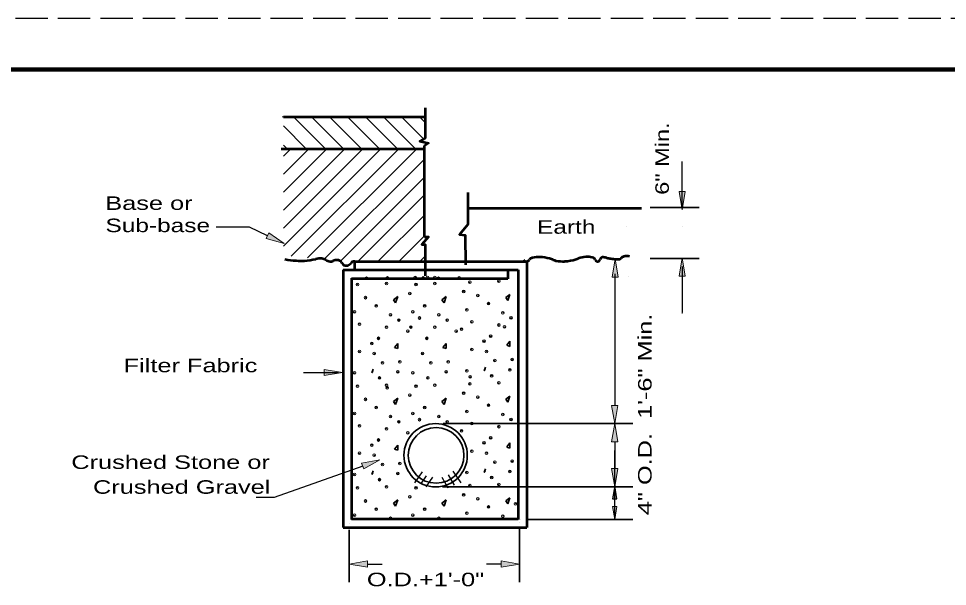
# Model space of a CAD drawing. Extents: x 36 to 71.3, y 0.3 to 22.3.
# Drawn here: x 52.91 to 62.04, y 16.74 to 22.32 of the extents above; entities that cross this region are included whole.
import ezdxf

# ---------------------------------------------------------------- set-up
doc = ezdxf.new("R2010")
doc.units = 0
doc.header["$LTSCALE"] = 0.053
doc.header["$PDMODE"] = 32
doc.header["$PDSIZE"] = 0.0265
doc.linetypes.add('LONG_DASHED', pattern=[7.5, 6, -1.5])
for name, color, linetype, lineweight in [('1', 7, 'Continuous', 13), ('2', 7, 'Continuous', 13), ('4', 7, 'Continuous', 13)]:
    doc.layers.add(name, color=color, linetype=linetype, lineweight=lineweight)

msp = doc.modelspace()

# ---------------------------------------------------------------- hatches: boundary and pattern name
at = {"layer": '1'}
for points in [[(59.40475, 20.6235), (59.46475, 20.6235), (59.43475, 20.4435), (59.43475, 20.4435)], [(58.74733, 19.78192), (58.80733, 19.78192), (58.77733, 19.96192), (58.77733, 19.96192)], [(59.40475, 19.78917), (59.46475, 19.78917), (59.43475, 19.96917), (59.43475, 19.96917)], [(56.34283, 16.98942), (56.34283, 16.92942), (56.16292, 16.95942), (56.16292, 16.95942)], [(57.655, 16.98942), (57.655, 16.92942), (57.835, 16.95942), (57.835, 16.95942)]]:
    msp.add_hatch(color=256, dxfattribs=at).paths.add_polyline_path(points)
at = {"layer": '2'}
for points in [[(55.37283, 20.21533), (55.34692, 20.16117), (55.52225, 20.1105), (55.52225, 20.1105)], [(55.91717, 18.81358), (55.91717, 18.87358), (56.09717, 18.84358), (56.09717, 18.84358)], [(58.74208, 18.51975), (58.80208, 18.51975), (58.77208, 18.33975), (58.77208, 18.33975)], [(58.74208, 18.15983), (58.80208, 18.15983), (58.77208, 18.33975), (58.77208, 18.33975)], [(58.74208, 18.15983), (58.80208, 18.15983), (58.77208, 18.33975), (58.77208, 18.33975)], [(56.28483, 17.95075), (56.30492, 17.89425), (56.4645, 17.98267), (56.4645, 17.98267)], [(58.74208, 17.89733), (58.80208, 17.89733), (58.77208, 17.71733), (58.77208, 17.71733)], [(58.74208, 17.89733), (58.80208, 17.89733), (58.77208, 17.71733), (58.77208, 17.71733)], [(58.75108, 17.602), (58.79308, 17.602), (58.77208, 17.72792), (58.77208, 17.72792)], [(58.75108, 17.52425), (58.79308, 17.52425), (58.77208, 17.39833), (58.77208, 17.39833)]]:
    msp.add_hatch(color=256, dxfattribs=at).paths.add_polyline_path(points)

# ---------------------------------------------------------------- linework, layer by layer
at = {"layer": '1', "linetype": 'LONG_DASHED', "lineweight": 25}
msp.add_line((71.17325, 22.32408), (35.97325, 22.32408), dxfattribs=at)
at = {"layer": '1', "lineweight": 158}
msp.add_line((65.01858, 21.82408), (52.503, 21.82408), dxfattribs=at)
at = {"layer": '1'}
for p, q in [((55.50242, 21.35808), (56.90925, 21.35808)), ((56.90925, 21.35808), (55.53658, 21.35808)), ((56.93842, 21.09575), (56.93258, 21.1015)), ((59.43475, 19.60333), (59.43475, 19.42333))]:
    msp.add_line(p, q, dxfattribs=at)
at = {"layer": '1', "lineweight": 53}
for p, q in [((55.51567, 21.35808), (56.90925, 21.35808)), ((55.49475, 21.04417), (56.90267, 21.04417)), ((56.90225, 20.17425), (56.90225, 21.07158)), ((57.326, 20.46058), (59.03558, 20.46058)), ((56.214, 19.9355), (57.90708, 19.9355)), ((56.214, 19.9355), (56.214, 19.85508)), ((57.90708, 19.9355), (57.90708, 17.31933)), ((56.10183, 19.85217), (56.10183, 17.31933)), ((56.10183, 19.85217), (57.82375, 19.85217)), ((57.72133, 19.85217), (57.72133, 19.765)), ((57.82375, 19.85217), (57.82375, 17.39833)), ((56.18517, 19.76933), (56.18517, 17.39833)), ((56.18517, 19.76883), (57.72133, 19.76883)), ((56.18517, 17.40267), (57.82375, 17.40267)), ((56.10183, 17.31933), (57.90708, 17.31933))]:
    msp.add_line(p, q, dxfattribs=at)
at = {"layer": '1', "lineweight": 35}
for p, q in [((55.92933, 21.04417), (55.61542, 21.35808)), ((56.10608, 21.04417), (55.79217, 21.35808)), ((56.28283, 21.04417), (55.96892, 21.35808)), ((56.45967, 21.04417), (56.14575, 21.35808)), ((56.63642, 21.04417), (56.3225, 21.35808)), ((56.81317, 21.04417), (56.49925, 21.35808)), ((56.89483, 21.13933), (56.67608, 21.35808)), ((56.90925, 21.30167), (56.85283, 21.35808)), ((55.73967, 21.04417), (55.51567, 21.26825)), ((55.55117, 21.04417), (55.51567, 21.07967)), ((55.51567, 20.08625), (56.47358, 21.04417)), ((55.51567, 20.26308), (56.29675, 21.04417)), ((55.51567, 20.43983), (56.12, 21.04417)), ((55.51567, 20.61658), (55.94325, 21.04417)), ((55.51567, 20.79342), (55.7665, 21.04417)), ((55.51567, 20.97017), (55.58967, 21.04417)), ((55.59358, 19.98742), (56.65033, 21.04417)), ((55.75367, 19.97067), (56.82708, 21.04417)), ((55.92425, 19.96458), (56.90225, 20.9425)), ((56.07908, 19.94258), (56.90225, 20.76575)), ((56.24175, 19.92842), (56.90225, 20.589)), ((59.121, 20.46525), (59.60417, 20.46525)), ((56.45483, 19.94358), (56.90225, 20.391)), ((56.65842, 19.94167), (56.90225, 20.18558)), ((56.86758, 19.94475), (56.90225, 19.9795)), ((59.121, 19.96383), (59.60417, 19.96383)), ((56.639, 19.58892), (56.599, 19.55892)), ((56.599, 19.55892), (56.619, 19.52892)), ((56.619, 19.529), (56.639, 19.589)), ((57.11433, 19.58892), (57.07433, 19.55892)), ((57.07433, 19.55892), (57.09433, 19.52892)), ((57.09433, 19.529), (57.11433, 19.589)), ((57.74292, 19.61017), (57.70292, 19.58017)), ((57.70292, 19.58017), (57.72292, 19.55017)), ((57.72292, 19.55025), (57.74292, 19.61025)), ((56.63908, 19.129), (56.60908, 19.089)), ((56.60908, 19.08892), (56.63908, 19.07892)), ((56.639, 19.079), (56.639, 19.129)), ((57.11442, 19.129), (57.08442, 19.089)), ((57.08442, 19.08892), (57.11442, 19.07892)), ((57.11433, 19.079), (57.11433, 19.129)), ((57.743, 19.15025), (57.713, 19.11025)), ((57.713, 19.11017), (57.743, 19.10017)), ((57.74292, 19.10025), (57.74292, 19.15025)), ((56.38375, 18.83892), (56.39817, 18.87492)), ((56.39817, 18.85125), (56.38375, 18.83892)), ((57.48767, 18.86017), (57.50208, 18.89617)), ((57.50208, 18.8725), (57.48767, 18.86017)), ((56.639, 18.58892), (56.599, 18.55892)), ((56.599, 18.55892), (56.619, 18.52892)), ((56.619, 18.529), (56.639, 18.589)), ((57.11433, 18.58892), (57.07433, 18.55892)), ((57.07433, 18.55892), (57.09433, 18.52892)), ((57.09433, 18.529), (57.11433, 18.589)), ((57.74292, 18.61017), (57.70292, 18.58017)), ((57.70292, 18.58017), (57.72292, 18.55017)), ((57.72292, 18.55025), (57.74292, 18.61025)), ((56.63908, 18.129), (56.60908, 18.089)), ((56.60908, 18.08892), (56.63908, 18.07892)), ((56.639, 18.079), (56.639, 18.129)), ((57.743, 18.15025), (57.713, 18.11025)), ((57.713, 18.11017), (57.743, 18.10017)), ((57.74292, 18.10025), (57.74292, 18.15025)), ((57.48767, 17.86017), (57.50208, 17.89617)), ((56.38375, 17.83892), (56.39817, 17.87492)), ((56.39817, 17.85125), (56.38375, 17.83892)), ((57.50208, 17.8725), (57.48767, 17.86017)), ((56.639, 17.58892), (56.599, 17.55892)), ((56.599, 17.55892), (56.619, 17.52892)), ((56.619, 17.529), (56.639, 17.589)), ((57.11433, 17.58892), (57.07433, 17.55892)), ((57.07433, 17.55892), (57.09433, 17.52892)), ((57.09433, 17.529), (57.11433, 17.589)), ((57.74292, 17.61017), (57.70292, 17.58017)), ((57.70292, 17.58017), (57.72292, 17.55017)), ((57.72292, 17.55025), (57.74292, 17.61025)), ((57.91108, 17.39833), (58.95208, 17.39833)), ((56.16292, 17.29392), (56.16292, 16.77942)), ((57.835, 17.302), (57.835, 16.77942))]:
    msp.add_line(p, q, dxfattribs=at)
at = {"layer": '1', "lineweight": 25}
for p, q in [((56.90225, 21.04258), (56.90225, 21.08042)), ((59.43475, 20.46492), (59.43475, 20.91817)), ((59.43475, 19.88708), (59.43475, 19.43383)), ((56.8795, 17.86642), (56.80358, 17.75667)), ((56.86525, 17.74458), (56.92133, 17.82692)), ((56.97975, 17.81317), (56.91475, 17.71717)), ((57.07325, 17.814), (57.13158, 17.70908)), ((57.136, 17.835), (57.1955, 17.73492)), ((57.18225, 17.87367), (57.25825, 17.75667)), ((56.34292, 16.95942), (56.48633, 16.95942)), ((57.655, 16.95942), (57.51158, 16.95942))]:
    msp.add_line(p, q, dxfattribs=at)
at = {"layer": '1', "lineweight": 53}
for points in [[(56.90925, 21.44683), (56.90925, 21.14667), (56.85533, 21.11925), (56.94342, 21.09908), (56.90267, 21.07158)], [(57.32733, 20.61225), (57.32733, 20.29833), (57.24542, 20.20008), (57.30075, 20.19367), (57.306, 19.90308)], [(56.90267, 20.17675), (56.94342, 20.17675), (56.87517, 20.10167), (56.90925, 20.10167), (56.90925, 19.79425)]]:
    msp.add_lwpolyline(points, dxfattribs=at)
at = {"layer": '1'}
for points in [[(59.40475, 20.6235), (59.46475, 20.6235), (59.43475, 20.4435), (59.43475, 20.4435)], [(58.74733, 19.78192), (58.80733, 19.78192), (58.77733, 19.96192), (58.77733, 19.96192)], [(59.40475, 19.78917), (59.46475, 19.78917), (59.43475, 19.96917), (59.43475, 19.96917)], [(56.34283, 16.98942), (56.34283, 16.92942), (56.16292, 16.95942), (56.16292, 16.95942)], [(57.655, 16.98942), (57.655, 16.92942), (57.835, 16.95942), (57.835, 16.95942)]]:
    msp.add_lwpolyline(points, close=True, dxfattribs=at)
at = {"layer": '1', "lineweight": 25}
msp.add_lwpolyline([(58.77208, 19.81275), (58.77208, 19.27417), (58.77208, 18.51683)], dxfattribs=at)
at = {"layer": '1', "lineweight": 35}
for centre, radius in [((57.01217, 18.02867), 0.31134), ((57.01658, 18.02775), 0.27355)]:
    msp.add_circle(centre, radius, dxfattribs=at)
at = {"layer": '1', "lineweight": 53}
for centre, radius, start, end in [((55.72067, 21.05367), 1.11355, 260.16329, 265.88503), ((55.68317, 20.53492), 0.59345, 265.90224, 273.7448), ((55.67308, 20.68308), 0.74198, 273.77126, 282.47695), ((55.87758, 19.75758), 0.20588, 85.82566, 102.39144), ((55.8865, 19.87742), 0.08569, 57.54698, 85.94234), ((55.98267, 20.02833), 0.09327, 237.44355, 264.65422), ((55.97958, 19.99517), 0.05994, 264.67221, 294.75702), ((56.04325, 19.85742), 0.09183, 90.63316, 114.85454), ((56.04283, 19.89467), 0.05456, 27.93418, 90.57138), ((56.13433, 19.94317), 0.049, 207.91366, 274.42583), ((56.13392, 19.94717), 0.05296, 274.54196, 324.33687), ((56.21458, 19.88908), 0.04644, 90.70129, 144.16646), ((56.21558, 19.8745), 0.06098, 88.55141, 91.44859), ((57.90208, 19.96767), 0.03259, 213.77868, 278.82211), ((57.90075, 19.97592), 0.04094, 278.90671, 323.33822), ((57.97342, 19.92167), 0.04977, 103.08754, 143.20645), ((58.02675, 19.69575), 0.28192, 87.60962, 103.24152), ((58.01975, 19.54183), 0.43603, 74.97604, 87.53164), ((58.05742, 19.68208), 0.29079, 67.65328, 74.9899), ((58.229, 20.09983), 0.16085, 247.72134, 257.59119), ((58.25958, 20.23725), 0.30166, 257.51865, 273.93896), ((58.24358, 20.46333), 0.52827, 273.98822, 286.38181), ((58.31675, 20.21758), 0.2719, 286.1872, 290.53634), ((58.52483, 19.66625), 0.31742, 106.76379, 110.78416), ((58.50592, 19.728), 0.25285, 90.01884, 106.70157), ((58.50575, 19.82108), 0.15976, 68.94446, 89.97717), ((58.55267, 19.94275), 0.02933, 17.2929, 69.01188), ((58.6035, 19.95867), 0.02395, 197.33123, 255.00704), ((58.60375, 19.95917), 0.02455, 254.92076, 348.154), ((58.65567, 19.94833), 0.0285, 83.42471, 168.22821), ((58.62492, 19.68733), 0.29133, 76.13512, 83.30209), ((58.77742, 20.30692), 0.34679, 256.20555, 262.77649), ((58.90383, 21.29558), 1.34344, 262.73188, 265.11598), ((58.80392, 20.13425), 0.17782, 265.31277, 271.86997), ((58.80883, 19.98992), 0.03346, 271.56977, 312.63735), ((58.88842, 19.90392), 0.08372, 107.19733, 132.83446), ((58.88708, 19.90733), 0.08005, 89.8769, 107.00639), ((58.88742, 19.84558), 0.14184, 77.24515, 90.07447)]:
    msp.add_arc(centre, radius, start, end, dxfattribs=at)
at = {"layer": '1'}
for p in [(56.24367, 19.709), (56.33225, 19.76933), (56.529, 19.719), (56.53733, 19.77283), (56.81133, 19.77817), (56.819, 19.709), (56.89083, 19.77283), (56.93325, 19.77642), (57.004, 19.77642), (57.00433, 19.719), (57.03933, 19.76933), (57.24442, 19.77283), (57.34758, 19.73025), (57.63292, 19.74025), (56.759, 19.619), (57.28758, 19.64025), (56.32375, 19.579), (57.42767, 19.60025), (56.21367, 19.439), (56.429, 19.499), (56.789, 19.439), (56.90433, 19.499), (57.31758, 19.46025), (57.53292, 19.52025), (56.569, 19.409), (56.64908, 19.359), (56.85433, 19.379), (57.04433, 19.409), (57.12442, 19.359), (57.67292, 19.43025), (57.753, 19.38025), (56.26367, 19.319), (56.529, 19.289), (56.76967, 19.29017), (57.00433, 19.289), (57.26767, 19.27025), (57.36758, 19.34025), (57.63292, 19.31025), (57.68942, 19.2915), (56.449, 19.179), (56.73908, 19.249), (56.92433, 19.179), (57.21442, 19.249), (57.55292, 19.20025), (56.38367, 19.129), (57.36758, 19.07025), (57.48758, 19.15025), (56.26367, 19.049), (56.409, 19.029), (56.88433, 19.029), (57.51292, 19.05025), (56.48908, 18.939), (56.659, 18.949), (56.96442, 18.939), (57.13433, 18.949), (57.593, 18.96025), (57.76292, 18.97025), (56.21367, 18.839), (56.639, 18.849), (56.789, 18.839), (57.11433, 18.849), (57.31758, 18.86025), (57.35008, 18.79975), (57.56292, 18.81025), (57.74292, 18.87025), (56.24367, 18.709), (56.459, 18.789), (56.529, 18.719), (56.819, 18.709), (56.93433, 18.789), (57.00433, 18.719), (57.34758, 18.73025), (57.63292, 18.74025), (56.53708, 18.69267), (56.759, 18.619), (57.28758, 18.64025), (56.32375, 18.579), (57.42767, 18.60025), (56.21367, 18.439), (56.429, 18.499), (56.789, 18.439), (56.90433, 18.499), (57.31758, 18.46025), (57.53292, 18.52025), (57.67292, 18.43025), (56.569, 18.409), (56.64908, 18.359), (56.85433, 18.379), (57.04433, 18.409), (57.12442, 18.359), (57.36758, 18.34025), (57.753, 18.38025), (56.26367, 18.319), (56.529, 18.289), (56.73908, 18.249), (57.26767, 18.27025), (57.63292, 18.31025), (56.449, 18.17892), (57.55292, 18.20017), (56.38367, 18.129), (57.36758, 18.07025), (57.48758, 18.15025), (56.26367, 18.049), (56.409, 18.029), (57.51292, 18.05025), (56.48908, 17.939), (56.659, 17.94892), (57.593, 17.96025), (57.76292, 17.97017), (56.21367, 17.839), (56.639, 17.849), (57.31758, 17.86025), (57.56292, 17.81025), (57.74292, 17.87025), (56.24367, 17.709), (56.459, 17.789), (56.529, 17.719), (56.819, 17.709), (57.34758, 17.73025), (57.63292, 17.74025), (56.759, 17.619), (57.28758, 17.64025), (56.32375, 17.579), (57.42767, 17.60025), (57.53292, 17.52025), (57.79717, 17.55217), (56.21367, 17.439), (56.429, 17.499), (56.789, 17.439), (56.90433, 17.499), (57.31758, 17.46025), (57.67292, 17.43025), (56.569, 17.409), (57.04433, 17.409)]:
    msp.add_point(p, dxfattribs=at)
at = {"layer": '2', "lineweight": 25}
for p, q in [((55.71283, 18.84358), (56.05408, 18.84358)), ((58.77208, 18.15983), (58.77208, 17.89733)), ((58.77208, 17.39833), (58.77208, 18.07733)), ((58.77208, 17.57833), (58.77208, 17.75833))]:
    msp.add_line(p, q, dxfattribs=at)
at = {"layer": '2'}
for p, q in [((58.77208, 18.77225), (58.77217, 18.77225)), ((58.77208, 18.33983), (58.77217, 18.33983)), ((58.77208, 18.33983), (58.77217, 18.33983)), ((58.83458, 18.33983), (58.95208, 18.33983)), ((58.77208, 18.15983), (58.77208, 17.97983)), ((58.70958, 17.71733), (58.59208, 17.71733)), ((58.77208, 17.71733), (58.77217, 17.71733)), ((58.77208, 17.71733), (58.77217, 17.71733)), ((58.77208, 17.39833), (58.77217, 17.39833)), ((58.77208, 17.39833), (58.77217, 17.39833)), ((58.83458, 17.39833), (58.95208, 17.39833))]:
    msp.add_line(p, q, dxfattribs=at)
at = {"layer": '2', "lineweight": 35}
for p, q in [((57.085, 18.33983), (58.95208, 18.33983)), ((57.07867, 17.71733), (58.95208, 17.71733))]:
    msp.add_line(p, q, dxfattribs=at)
at = {"layer": '2', "lineweight": 25}
for points in [[(55.35992, 20.18825), (55.18325, 20.27275), (54.85633, 20.27275)], [(56.29492, 17.9225), (55.4265, 17.61467), (55.2465, 17.61467)]]:
    msp.add_lwpolyline(points, dxfattribs=at)
at = {"layer": '2'}
for points in [[(55.37283, 20.21533), (55.34692, 20.16117), (55.52225, 20.1105), (55.52225, 20.1105)], [(55.91717, 18.81358), (55.91717, 18.87358), (56.09717, 18.84358), (56.09717, 18.84358)], [(58.74208, 18.51975), (58.80208, 18.51975), (58.77208, 18.33975), (58.77208, 18.33975)], [(58.74208, 18.15983), (58.80208, 18.15983), (58.77208, 18.33975), (58.77208, 18.33975)], [(58.74208, 18.15983), (58.80208, 18.15983), (58.77208, 18.33975), (58.77208, 18.33975)], [(56.28483, 17.95075), (56.30492, 17.89425), (56.4645, 17.98267), (56.4645, 17.98267)], [(58.74208, 17.89733), (58.80208, 17.89733), (58.77208, 17.71733), (58.77208, 17.71733)], [(58.74208, 17.89733), (58.80208, 17.89733), (58.77208, 17.71733), (58.77208, 17.71733)], [(58.75108, 17.52425), (58.79308, 17.52425), (58.77208, 17.39833), (58.77208, 17.39833)]]:
    msp.add_lwpolyline(points, close=True, dxfattribs=at)
at = {"layer": '2', "lineweight": 25}
msp.add_lwpolyline([(58.75108, 17.602), (58.79308, 17.602), (58.77208, 17.72792), (58.77208, 17.72792)], close=True, dxfattribs=at)
at = {"layer": '4'}
for p, q in [((58.88358, 20.27942), (58.88367, 20.27942)), ((59.43475, 20.27942), (59.43483, 20.27942)), ((58.77908, 19.77608), (58.77917, 19.77608)), ((58.90525, 19.78333), (58.90533, 19.78333)), ((58.90525, 19.78333), (58.90533, 19.78333)), ((59.43475, 19.78333), (59.43483, 19.78333)), ((58.77208, 18.77225), (58.77217, 18.77225)), ((57.0225, 18.33983), (57.02258, 18.33983)), ((57.01617, 17.71733), (57.01625, 17.71733)), ((56.16292, 17.35642), (56.163, 17.35642)), ((57.835, 17.3645), (57.83508, 17.3645)), ((57.84858, 17.39833), (57.84867, 17.39833)), ((57.835, 16.95942), (57.83508, 16.95942))]:
    msp.add_line(p, q, dxfattribs=at)

# ---------------------------------------------------------------- texts
at = {"layer": '1', "width": 1.3}
msp.add_text('6" Min.', height=0.133, rotation=90, dxfattribs=at).set_placement((59.30458, 20.59083))
at = {"layer": '1', "width": 1.4}
msp.add_text('O.D.+1\'-0"', height=0.133, dxfattribs=at).set_placement((56.33608, 16.74067))
at = {"layer": '2'}
for s, width, p in [('Base or', 1.4, (53.76483, 20.44217)), ('Sub-base', 1.35, (53.76683, 20.22342)), ('Earth', 1.35, (58.00883, 20.208)), ('Filter Fabric', 1.4, (53.94525, 18.84558)), ('Crushed Stone or', 1.4, (53.431, 17.89433)), ('Crushed Gravel', 1.4, (53.64425, 17.65008))]:
    msp.add_text(s, height=0.133, dxfattribs=dict(at, width=width)).set_placement(p)
at = {"layer": '2', "width": 1.4}
msp.add_text('4" O.D.  1\'-6" Min.', height=0.133, rotation=90, dxfattribs=at).set_placement((59.13492, 17.44008))

doc.saveas('drawing.dxf')
